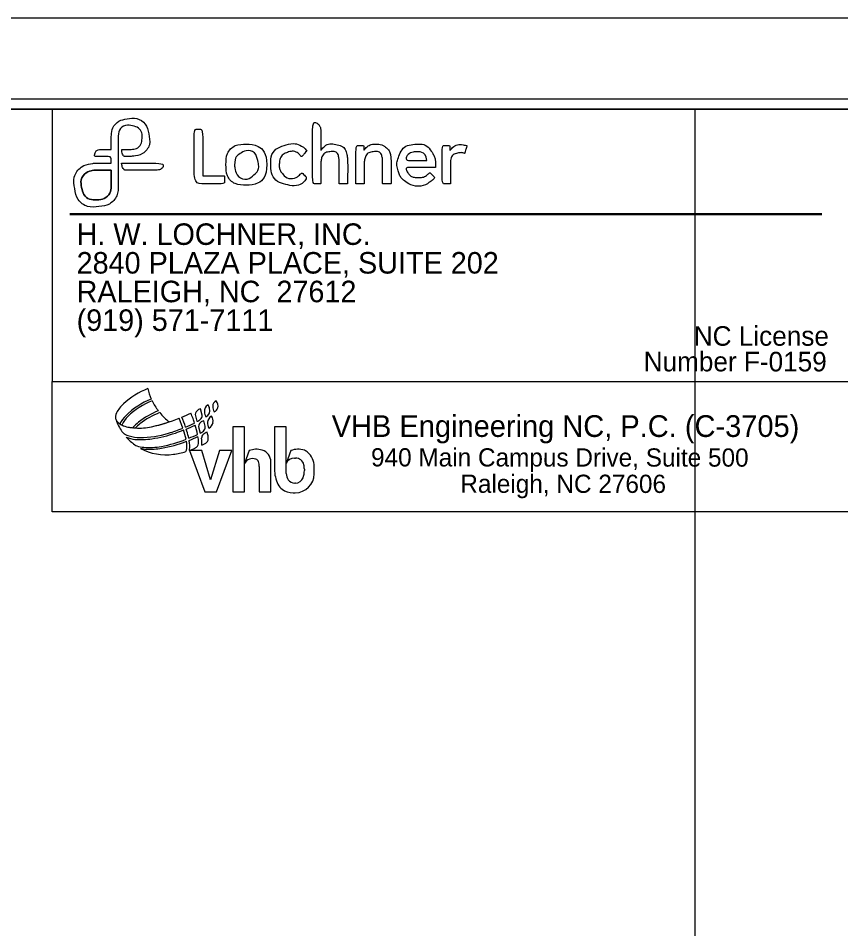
# Model space of a CAD drawing. Extents: x 2044275 to 2045958, y 759228 to 760388.
# Drawn here: x 2045534.8 to 2045738.1, y 760098.4 to 760323.3 of the extents above; entities that cross this region are included whole.
import ezdxf

# ---------------------------------------------------------------- set-up
doc = ezdxf.new("R2010")
doc.units = 0
for name, color, linetype in [('Default', 7, 'Continuous'), ('Old_Level_1', 7, 'Continuous'), ('Old_Level_4', 7, 'Continuous'), ('Sheet Clip Boundary CELL', 7, 'Continuous'), ('Sheet Cutting Line CELL', 7, 'Continuous'), ('Sheet Plan CELL', 7, 'Continuous'), ('Sheet Plot Border Inside CELL', 7, 'Continuous'), ('Sheet Plot Border Outside CELL', 7, 'Continuous')]:
    doc.layers.add(name, color=color, linetype=linetype)

msp = doc.modelspace()

# ---------------------------------------------------------------- linework, layer by layer
at = {"layer": 'Default'}
for points in [[(2045557.79, 760287.5), (2045557.67, 760287.5), (2045557.57, 760287.5), (2045557.48, 760287.5), (2045556.39, 760287.5), (2045555.31, 760287.51), (2045554.22, 760287.5), (2045553.85, 760287.49), (2045553.48, 760287.46), (2045553.11, 760287.4), (2045550.27, 760286.91), (2045548.28, 760284.04), (2045548.8, 760281.21), (2045549.34, 760278.3), (2045551.88, 760276.43), (2045554.83, 760276.76), (2045557.44, 760277.05), (2045559.54, 760279.39), (2045559.54, 760282), (2045559.54, 760285.94), (2045559.53, 760289.87), (2045559.54, 760293.8), (2045559.54, 760295.72), (2045561.33, 760297.13), (2045563.19, 760296.67), (2045564.59, 760296.32), (2045565.56, 760294.99), (2045565.44, 760293.58), (2045565.3, 760292.1), (2045564.11, 760290.94), (2045562.63, 760290.88), (2045561.99, 760290.85), (2045561.34, 760290.87), (2045560.7, 760290.86), (2045560.6, 760290.86), (2045560.5, 760290.85), (2045560.38, 760290.84), (2045560.44, 760290.24), (2045560.58, 760289.71), (2045560.93, 760289.24), (2045560.97, 760289.18), (2045561.07, 760289.14), (2045561.14, 760289.14), (2045561.78, 760289.15), (2045562.41, 760289.12), (2045563.04, 760289.19), (2045565.68, 760289.46), (2045567.67, 760292), (2045567.06, 760294.8), (2045566.51, 760297.3), (2045564.2, 760298.82), (2045561.65, 760298.41), (2045559.65, 760298.09), (2045557.96, 760296.28), (2045557.84, 760294.26), (2045557.78, 760293.24), (2045557.82, 760292.22), (2045557.81, 760291.2), (2045557.8, 760291.1), (2045557.81, 760291), (2045557.81, 760290.86), (2045557.68, 760290.86), (2045557.58, 760290.86), (2045557.49, 760290.86), (2045556.77, 760290.86), (2045556.05, 760290.87), (2045555.33, 760290.86), (2045554.58, 760290.86), (2045553.95, 760290.39), (2045553.76, 760289.67), (2045553.71, 760289.5), (2045553.71, 760289.32), (2045553.69, 760289.12), (2045555.09, 760289.12), (2045556.43, 760289.12), (2045557.79, 760289.12), (2045557.79, 760288.58), (2045557.79, 760288.06), (2045557.79, 760287.5)], [(2045614.16, 760282.34), (2045614.86, 760282.34), (2045615.53, 760282.34), (2045616.22, 760282.34), (2045616.22, 760282.41), (2045616.23, 760282.47), (2045616.23, 760282.53), (2045616.23, 760284.37), (2045616.24, 760286.21), (2045616.23, 760288.06), (2045616.22, 760288.45), (2045616.19, 760288.84), (2045616.12, 760289.22), (2045615.85, 760290.62), (2045615.12, 760291.67), (2045613.67, 760292.02), (2045612.17, 760292.39), (2045610.82, 760292.07), (2045609.77, 760290.85), (2045609.73, 760290.79), (2045609.68, 760290.74), (2045609.57, 760290.63), (2045609.57, 760290.81), (2045609.57, 760290.9), (2045609.57, 760290.99), (2045609.57, 760292.57), (2045609.58, 760294.14), (2045609.57, 760295.72), (2045609.57, 760295.93), (2045609.53, 760296.15), (2045609.46, 760296.35), (2045609.18, 760297.1), (2045608.24, 760297.66), (2045607.53, 760297.5), (2045607.53, 760292.45), (2045607.53, 760287.4), (2045607.53, 760282.34), (2045608.22, 760282.34), (2045608.89, 760282.34), (2045609.57, 760282.34), (2045609.57, 760282.47), (2045609.57, 760282.57), (2045609.57, 760282.68), (2045609.57, 760284.15), (2045609.57, 760285.62), (2045609.58, 760287.09), (2045609.58, 760287.46), (2045609.61, 760287.84), (2045609.68, 760288.2), (2045609.91, 760289.4), (2045610.69, 760290.17), (2045611.84, 760290.3), (2045612.97, 760290.43), (2045613.84, 760289.95), (2045614.07, 760288.75), (2045614.12, 760288.49), (2045614.15, 760288.22), (2045614.15, 760287.95), (2045614.16, 760286.83), (2045614.16, 760285.7), (2045614.16, 760284.57), (2045614.16, 760283.84), (2045614.16, 760283.1), (2045614.16, 760282.34)], [(2045580.43, 760284.32), (2045580.43, 760288.19), (2045580.43, 760292.03), (2045580.43, 760295.87), (2045579.69, 760295.87), (2045578.99, 760295.87), (2045578.27, 760295.87), (2045578.27, 760291.36), (2045578.27, 760286.85), (2045578.27, 760282.34), (2045580.79, 760282.34), (2045583.29, 760282.34), (2045585.82, 760282.34), (2045585.82, 760282.92), (2045585.81, 760283.48), (2045585.82, 760284.04), (2045585.83, 760284.27), (2045585.77, 760284.33), (2045585.53, 760284.33), (2045583.95, 760284.32), (2045582.36, 760284.32), (2045580.77, 760284.32), (2045580.67, 760284.32), (2045580.57, 760284.32), (2045580.43, 760284.32)], [(2045596.26, 760287.11), (2045596.26, 760289.98), (2045594.09, 760292.17), (2045591.22, 760292.17), (2045588.35, 760292.17), (2045586.17, 760289.99), (2045586.17, 760287.13), (2045586.17, 760284.25), (2045588.33, 760282.06), (2045591.17, 760282.06), (2045594.09, 760282.06), (2045596.26, 760284.21), (2045596.26, 760287.11)], [(2045606.12, 760290.48), (2045605.02, 760291.98), (2045602.63, 760292.59), (2045600.52, 760291.86), (2045598.38, 760291.11), (2045597.12, 760289.12), (2045597.25, 760286.68), (2045597.36, 760284.54), (2045598.83, 760282.73), (2045600.91, 760282.23), (2045603.05, 760281.71), (2045605.13, 760282.35), (2045606.2, 760283.82), (2045605.77, 760284.27), (2045605.35, 760284.72), (2045604.96, 760285.13), (2045604.79, 760284.99), (2045604.63, 760284.87), (2045604.49, 760284.73), (2045603.25, 760283.54), (2045601.08, 760283.67), (2045600.02, 760285.02), (2045599.46, 760285.73), (2045599.31, 760286.55), (2045599.36, 760287.44), (2045599.44, 760288.66), (2045600.24, 760289.76), (2045601.36, 760290.14), (2045602.53, 760290.55), (2045603.84, 760290.19), (2045604.66, 760289.24), (2045604.7, 760289.19), (2045604.74, 760289.13), (2045604.82, 760289.02), (2045605.27, 760289.52), (2045605.68, 760289.99), (2045606.12, 760290.48)], [(2045618.25, 760282.34), (2045618.94, 760282.34), (2045619.62, 760282.34), (2045620.31, 760282.34), (2045620.31, 760282.46), (2045620.31, 760282.57), (2045620.31, 760282.67), (2045620.31, 760284.18), (2045620.3, 760285.68), (2045620.31, 760287.19), (2045620.31, 760287.52), (2045620.34, 760287.85), (2045620.4, 760288.17), (2045620.62, 760289.38), (2045621.41, 760290.16), (2045622.56, 760290.3), (2045623.65, 760290.43), (2045624.55, 760289.99), (2045624.79, 760288.78), (2045624.84, 760288.54), (2045624.88, 760288.29), (2045624.88, 760288.04), (2045624.88, 760286.24), (2045624.88, 760284.44), (2045624.88, 760282.64), (2045624.88, 760282.54), (2045624.88, 760282.44), (2045624.88, 760282.34), (2045625.59, 760282.34), (2045626.27, 760282.34), (2045626.95, 760282.34), (2045626.95, 760282.45), (2045626.95, 760282.55), (2045626.95, 760282.64), (2045626.95, 760284.34), (2045626.96, 760286.04), (2045626.95, 760287.73), (2045626.95, 760288.11), (2045626.94, 760288.5), (2045626.9, 760288.87), (2045626.78, 760289.89), (2045626.41, 760290.8), (2045625.58, 760291.46), (2045625, 760291.92), (2045624.31, 760292.12), (2045623.58, 760292.15), (2045622.31, 760292.21), (2045621.22, 760291.83), (2045620.4, 760290.82), (2045620.37, 760290.78), (2045620.33, 760290.74), (2045620.24, 760290.65), (2045620.24, 760291.09), (2045620.24, 760291.48), (2045620.24, 760291.87), (2045619.56, 760291.87), (2045618.92, 760291.87), (2045618.25, 760291.87), (2045618.25, 760288.69), (2045618.25, 760285.53), (2045618.25, 760282.34)], [(2045637.94, 760286.41), (2045637.94, 760286.76), (2045637.95, 760287.08), (2045637.94, 760287.4), (2045637.88, 760288.34), (2045637.66, 760289.23), (2045637.15, 760290.03), (2045636.16, 760291.6), (2045634.71, 760292.28), (2045632.87, 760292.14), (2045630.9, 760291.99), (2045629.57, 760290.94), (2045628.87, 760289.12), (2045628.38, 760287.86), (2045628.39, 760286.56), (2045628.8, 760285.28), (2045629.1, 760284.35), (2045629.65, 760283.59), (2045630.43, 760283.02), (2045632.23, 760281.7), (2045635.05, 760281.73), (2045636.9, 760283.08), (2045637.21, 760283.31), (2045637.49, 760283.58), (2045637.8, 760283.85), (2045637.36, 760284.32), (2045636.97, 760284.74), (2045636.56, 760285.17), (2045636.48, 760285.1), (2045636.41, 760285.04), (2045636.34, 760284.97), (2045635.49, 760284.22), (2045634.5, 760283.86), (2045633.36, 760283.93), (2045632.42, 760283.98), (2045631.62, 760284.33), (2045631.08, 760285.13), (2045630.82, 760285.5), (2045630.67, 760285.92), (2045630.64, 760286.41), (2045631.88, 760286.41), (2045633.08, 760286.41), (2045634.29, 760286.41), (2045635.5, 760286.41), (2045636.71, 760286.41), (2045637.94, 760286.41)], [(2045645.65, 760291.72), (2045645.65, 760291.76), (2045645.65, 760291.79), (2045645.65, 760291.82), (2045645.61, 760291.83), (2045645.56, 760291.83), (2045645.52, 760291.84), (2045644.01, 760292.21), (2045642.67, 760291.95), (2045641.6, 760290.74), (2045641.58, 760290.72), (2045641.55, 760290.71), (2045641.48, 760290.68), (2045641.48, 760291.1), (2045641.48, 760291.48), (2045641.48, 760291.87), (2045640.82, 760291.87), (2045640.2, 760291.87), (2045639.57, 760291.87), (2045639.57, 760288.68), (2045639.57, 760285.51), (2045639.57, 760282.34), (2045640.26, 760282.34), (2045640.92, 760282.34), (2045641.62, 760282.34), (2045641.62, 760282.45), (2045641.62, 760282.55), (2045641.62, 760282.65), (2045641.62, 760284.28), (2045641.62, 760285.91), (2045641.62, 760287.53), (2045641.63, 760288.84), (2045642.48, 760289.82), (2045643.77, 760290.03), (2045644.25, 760290.11), (2045644.7, 760290.04), (2045645.16, 760289.86), (2045645.19, 760289.95), (2045645.21, 760290.04), (2045645.23, 760290.12), (2045645.37, 760290.65), (2045645.51, 760291.19), (2045645.65, 760291.72)], [(2045588.27, 760286.98), (2045588.31, 760288.2), (2045588.65, 760289.15), (2045589.58, 760289.8), (2045591.01, 760290.8), (2045593.51, 760290.37), (2045594.06, 760287.99), (2045594.34, 760286.75), (2045594.13, 760285.59), (2045593.18, 760284.68), (2045591.56, 760283.15), (2045588.92, 760283.99), (2045588.39, 760286.18), (2045588.32, 760286.48), (2045588.3, 760286.8), (2045588.27, 760286.98)], [(2045635.77, 760288.1), (2045634.08, 760288.1), (2045632.38, 760288.1), (2045630.69, 760288.1), (2045630.57, 760289.04), (2045631.77, 760290.19), (2045632.97, 760290.28), (2045634.53, 760290.39), (2045635.74, 760289.46), (2045635.77, 760288.1)], [(2045560.39, 760287.49), (2045560.45, 760286.9), (2045560.6, 760286.36), (2045560.95, 760285.9), (2045561.01, 760285.83), (2045561.14, 760285.78), (2045561.24, 760285.78), (2045563.85, 760285.77), (2045566.46, 760285.76), (2045569.07, 760285.77), (2045570.01, 760285.78), (2045570.79, 760286.63), (2045570.65, 760287.49), (2045567.24, 760287.49), (2045563.84, 760287.49), (2045560.39, 760287.49)], [(2045557.79, 760285.76), (2045557.69, 760285.76), (2045557.62, 760285.77), (2045557.55, 760285.77), (2045556.4, 760285.77), (2045555.24, 760285.77), (2045554.09, 760285.77), (2045553.87, 760285.77), (2045553.64, 760285.74), (2045553.42, 760285.7), (2045551.5, 760285.37), (2045550.13, 760283.37), (2045550.51, 760281.48), (2045550.89, 760279.6), (2045552.4, 760278.39), (2045554.32, 760278.45), (2045556.12, 760278.49), (2045557.72, 760280.03), (2045557.79, 760281.82), (2045557.83, 760283.08), (2045557.8, 760284.35), (2045557.8, 760285.61), (2045557.8, 760285.65), (2045557.79, 760285.69), (2045557.79, 760285.76)], [(2045557.79, 760285.76), (2045557.79, 760285.69), (2045557.8, 760285.65), (2045557.8, 760285.61), (2045557.8, 760284.35), (2045557.83, 760283.08), (2045557.79, 760281.82), (2045557.72, 760280.03), (2045556.12, 760278.49), (2045554.32, 760278.45), (2045552.4, 760278.39), (2045550.89, 760279.6), (2045550.51, 760281.48), (2045550.13, 760283.37), (2045551.5, 760285.37), (2045553.42, 760285.7), (2045553.64, 760285.74), (2045553.87, 760285.77), (2045554.09, 760285.77), (2045555.24, 760285.77), (2045556.4, 760285.77), (2045557.55, 760285.77), (2045557.62, 760285.77), (2045557.69, 760285.76), (2045557.79, 760285.76)], [(2045557.79, 760285.76), (2045557.79, 760285.69), (2045557.8, 760285.65), (2045557.8, 760285.61), (2045557.8, 760284.35), (2045557.83, 760283.08), (2045557.79, 760281.82), (2045557.72, 760280.03), (2045556.12, 760278.49), (2045554.32, 760278.45), (2045552.4, 760278.39), (2045550.89, 760279.6), (2045550.51, 760281.48), (2045550.13, 760283.37), (2045551.5, 760285.37), (2045553.42, 760285.7), (2045553.64, 760285.74), (2045553.87, 760285.77), (2045554.09, 760285.77), (2045555.24, 760285.77), (2045556.4, 760285.77), (2045557.55, 760285.77), (2045557.62, 760285.77), (2045557.69, 760285.76), (2045557.79, 760285.76)]]:
    msp.add_open_spline(points, degree=3, dxfattribs=at)
at = {"layer": 'Old_Level_1'}
for p, q in [((2045547.59, 760275.01), (2045733.35, 760275.01)), ((2045547.59, 760274.82), (2045733.35, 760274.82))]:
    msp.add_line(p, q, dxfattribs=at)
at = {"layer": 'Old_Level_4'}
for p, q in [((2045543.25, 760300.8), (2045543.25, 760233.57)), ((2045543.25, 760233.57), (2045741.31, 760233.57)), ((2045543.25, 760201.37), (2045543.25, 760233.57)), ((2045543.25, 760233.57), (2045741.31, 760233.57)), ((2045580.28, 760225.24), (2045579.85, 760226.78)), ((2045575.52, 760222.03), (2045574.64, 760224.47)), ((2045578.61, 760225.09), (2045578.99, 760223.73)), ((2045579.45, 760222.06), (2045579.8, 760220.82)), ((2045581.04, 760222.52), (2045580.66, 760223.86)), ((2045590.77, 760222.35), (2045587.88, 760222.35)), ((2045587.88, 760222.35), (2045587.88, 760206.34)), ((2045601.04, 760222.35), (2045598.16, 760222.35)), ((2045598.16, 760222.35), (2045598.16, 760211.85)), ((2045577.12, 760216.47), (2045578.59, 760217.12)), ((2045580.2, 760216.47), (2045577.12, 760216.47)), ((2045577.12, 760216.47), (2045580.92, 760206.34)), ((2045582.37, 760209.24), (2045580.2, 760216.47)), ((2045584.54, 760216.47), (2045582.37, 760209.24)), ((2045583.82, 760206.34), (2045587.62, 760216.47)), ((2045587.62, 760216.47), (2045584.54, 760216.47)), ((2045591.89, 760216.47), (2045590.77, 760213.27)), ((2045602.17, 760216.47), (2045601.04, 760213.27)), ((2045597.28, 760206.34), (2045597.28, 760213.69)), ((2045603.08, 760214.64), (2045603.35, 760214.64)), ((2045594.39, 760212.54), (2045594.39, 760206.34)), ((2045605.53, 760211.86), (2045605.53, 760211.54)), ((2045607.96, 760210.74), (2045607.96, 760212.57)), ((2045603.34, 760208.45), (2045603.16, 760208.45)), ((2045580.92, 760206.34), (2045583.82, 760206.34)), ((2045587.88, 760206.34), (2045590.77, 760206.34)), ((2045594.39, 760206.34), (2045597.28, 760206.34)), ((2045602.73, 760206.06), (2045603.29, 760206.06)), ((2045741.31, 760201.37), (2045543.25, 760201.37))]:
    msp.add_line(p, q, dxfattribs=at)
for points in [[(2045590.77, 760206.34), (2045590.77, 760213.27), (2045590.77, 760222.35)], [(2045601.04, 760210.81), (2045601.04, 760213.27), (2045601.04, 760222.35)]]:
    msp.add_lwpolyline(points, dxfattribs=at)
for centre, major_axis, start_param, end_param in [((2045574.23, 760213.28), (19.94, 0), 1.950459, 2.306295), ((2045581.14, 760235.19), (14.69, 0), 3.374816, 3.559712), ((2045575, 760211.23), (19.42, 0), 1.955908, 2.345415), ((2045575, 760211.23), (18.92, 0), 1.954608, 2.331375), ((2045581.14, 760235.19), (14.69, 0), 3.593328, 3.791245), ((2045584.27, 760227.48), (1.36, 0), 1.950799, 3.19085), ((2045582.31, 760227.54), (1.89, 0), 6.010502, 6.978239), ((2045566.27, 760222.07), (8.08, 0), 2.306295, 2.663056), ((2045577.34, 760206.86), (20.99, 0), 1.956929, 2.223843), ((2045580.01, 760225.31), (1.42, 0), 2.340862, 3.293303), ((2045580.26, 760225.04), (1.78, 0), 1.805558, 2.340862), ((2045582.59, 760226.23), (1.78, 0), 2.069357, 3.26373), ((2045580.43, 760226.41), (1.78, 0), 5.158115, 6.583255), ((2045578.83, 760225.91), (3.46, 0), 0.300085, 0.573578), ((2045586.37, 760227.59), (3.46, 0), 3.190836, 3.597778), ((2045582.72, 760227.43), (1.47, 0), 5.088672, 6.010509), ((2045560.96, 760224.82), (2.1, 0), 2.663056, 3.487291), ((2045571.33, 760228.56), (13.12, 0), 3.487291, 3.49224), ((2045560, 760224.41), (1.05, 0), 3.492238, 3.942132), ((2045560, 760224.41), (1.05, 0), 3.492238, 3.942132), ((2045571.33, 760228.56), (13.12, 0), 3.492238, 3.737263), ((2045566.56, 760219.86), (7.35, 0), 2.345415, 2.685879), ((2045566.66, 760220), (6.82, 0), 2.331375, 2.717794), ((2045577.34, 760206.86), (20.46, 0), 1.949325, 2.223843), ((2045559.01, 760263.44), (41.98, 0), 4.923489, 5.093727), ((2045581.14, 760235.19), (14.69, 0), 3.829221, 4.05458), ((2045559.01, 760263.44), (41.98, 0), 5.110242, 5.168312), ((2045526.54, 760205.28), (52.48, 0), 0.330018, 0.379866), ((2045526.54, 760205.28), (54.92, 0), 0.355324, 0.381952), ((2045552.65, 760214.96), (27.07, 0), 0.312292, 0.355324), ((2045578.62, 760225.47), (1.78, 0), 4.922279, 5.445148), ((2045578.87, 760225.2), (1.42, 0), 5.445151, 6.311085), ((2045584.26, 760226.43), (3.46, 0), 3.26373, 3.631752), ((2045583.3, 760223.43), (1.68, 0), 1.982585, 3.114577), ((2045580.79, 760223.75), (2.2, 0), 6.124862, 6.873863), ((2045562.85, 760227.35), (5.14, 0), 3.942115, 4.117328), ((2045562.85, 760227.35), (5.14, 0), 3.942115, 4.535322), ((2045562.85, 760227.35), (5.14, 0), 4.225969, 4.535322), ((2045564.62, 760237.27), (15.22, 0), 4.535322, 4.613027), ((2045564.62, 760237.27), (15.22, 0), 4.535322, 4.657076), ((2045570.33, 760216.03), (9.45, 0), 2.223843, 2.440018), ((2045570.33, 760216.03), (8.91, 0), 2.223843, 2.396036), ((2045564.62, 760237.27), (15.22, 0), 4.657076, 4.923489), ((2045564.62, 760237.27), (15.22, 0), 4.657076, 4.923489), ((2045559.01, 760263.44), (41.98, 0), 4.923489, 5.030725), ((2045559.01, 760263.44), (44.58, 0), 5.007435, 5.091777), ((2045559.01, 760263.44), (44.6, 0), 5.107726, 5.162272), ((2045559.01, 760263.44), (45.1, 0), 5.106941, 5.160619), ((2045526.54, 760205.28), (52.48, 0), 0.309699, 0.320394), ((2045552.65, 760214.96), (27.07, 0), 0.205325, 0.293478), ((2045580.77, 760222.41), (1.36, 0), 2.294387, 3.400315), ((2045581.19, 760221.94), (1.99, 0), 1.838184, 2.294391), ((2045579.68, 760222.35), (1.36, 0), 5.669754, 6.410867), ((2045584.56, 760223.4), (2.94, 0), 3.114567, 3.617561), ((2045581.21, 760223.68), (1.78, 0), 5.137017, 6.124854), ((2045562.21, 760222.38), (2.1, 0), 3.737263, 4.155114), ((2045563.43, 760224.34), (4.41, 0), 4.155114, 4.433304), ((2045564.25, 760225.74), (6.51, 0), 4.281835, 4.626581), ((2045571.33, 760228.56), (13.12, 0), 3.869789, 4.084312), ((2045564.88, 760229.38), (9.66, 0), 4.433304, 4.717272), ((2045564.8, 760244.39), (24.67, 0), 4.717272, 5.007435), ((2045562.74, 760252.59), (33.59, 0), 4.866042, 5.043468), ((2045559.01, 760263.44), (45.06, 0), 5.043468, 5.091439), ((2045561.87, 760216.58), (14.69, 0), 0.186675, 0.34709), ((2045561.87, 760216.58), (15.39, 0), 0.192744, 0.309699), ((2045559.01, 760263.44), (47.44, 0), 5.100586, 5.150688), ((2045559.01, 760263.44), (47.96, 0), 5.098273, 5.148033), ((2045552.65, 760214.96), (27.07, 0), 0.162521, 0.185756), ((2045579.17, 760222.71), (1.99, 0), 5.034707, 5.66976), ((2045581.3, 760219.61), (1.15, 0), 2.288613, 3.208516), ((2045571.51, 760218.41), (8.71, 0), 6.218327, 6.411973), ((2045582.48, 760218.27), (2.94, 0), 1.905419, 2.288613), ((2045576.65, 760219.36), (5.14, 0), 6.258511, 6.615609), ((2045564.86, 760219.64), (2.1, 0), 4.084312, 4.375641), ((2045565.2, 760236.72), (17.53, 0), 4.626581, 4.866042), ((2045566.42, 760224.1), (6.82, 0), 4.375641, 4.631331), ((2045567.2, 760233.72), (16.48, 0), 4.631331, 4.896065), ((2045564.46, 760248.48), (31.49, 0), 4.896065, 5.098239), ((2045565.41, 760246.07), (29.39, 0), 4.878361, 5.095384), ((2045573.38, 760217.51), (3.15, 0), 5.862276, 6.364042), ((2045561.87, 760216.58), (14.69, 0), 0.080866, 0.152313), ((2045561.87, 760216.58), (15.39, 0), 0.08898, 0.158557), ((2045571.97, 760217.48), (5.25, 0), 6.089473, 6.37216), ((2045578.03, 760218.37), (1.36, 0), 5.129856, 6.17953), ((2045575.22, 760218.66), (4.2, 0), 6.17953, 6.445706), ((2045579.4, 760220.67), (2.94, 0), 4.991009, 5.49053), ((2045580.65, 760219.4), (1.15, 0), 5.49053, 6.137671), ((2045566.97, 760226.5), (9.66, 0), 4.511808, 4.670453), ((2045571.33, 760228.56), (13.12, 0), 4.213149, 4.853258), ((2045567.32, 760234.68), (17.84, 0), 4.670453, 4.878361), ((2045570, 760237.91), (22.57, 0), 4.853258, 4.99278), ((2045593.69, 760211.94), (4.88, 0), 1.271815, 1.948427), ((2045594.23, 760213.69), (3.04, 0), 6.283185, 7.555001), ((2045603.97, 760211.94), (4.88, 0), 1.243417, 1.948427), ((2045604.73, 760214.17), (2.52, 0), 0.841181, 1.243417), ((2045603.29, 760212.57), (4.67, 0), 0, 0.841181), ((2045592.76, 760212.33), (-2.2, 0), 4.330931, 5.84316), ((2045593.19, 760213.4), (-1.05, 0), 3.478495, 4.330931), ((2045590.72, 760212.54), (3.67, 0), 0, 0.336903), ((2045603.08, 760212.44), (2.2, 0), 1.570796, 2.75299), ((2045603.35, 760212.54), (2.1, 0), 0.218399, 1.570796), ((2045600.28, 760211.86), (5.25, 0), 6.283185, 6.501584), ((2045606.55, 760211.85), (-8.4, 0), 0, 0.452165), ((2045603.67, 760210.81), (-2.62, 0), 6.283185, 6.906012), ((2045603.29, 760210.74), (4.67, 0), 4.712389, 6.283185), ((2045600.28, 760211.54), (5.25, 0), 5.93764, 6.283185), ((2045603.16, 760210.44), (-1.99, 0), 0.622827, 1.570796), ((2045603.34, 760210.44), (1.99, 0), 4.712389, 5.93764), ((2045602.02, 760209.65), (-3.36, 0), 0.452165, 0.946963), ((2045602.73, 760210.64), (-4.58, 0), 0.946963, 1.570796)]:
    msp.add_ellipse(centre, major_axis=major_axis, ratio=0.999914, start_param=start_param, end_param=end_param, dxfattribs=at)
at = {"layer": 'Sheet Clip Boundary CELL'}
msp.add_lwpolyline([(2044491.34, 759250.8), (2045891.35, 759250.8), (2045891.35, 760089.31), (2045702.09, 760089.31), (2045702.09, 760300.8), (2044491.34, 760300.8)], close=True, dxfattribs=at)
at = {"layer": 'Sheet Cutting Line CELL'}
msp.add_line((2045958.35, 760323.28), (2044274.85, 760323.28), dxfattribs=at)
at = {"layer": 'Sheet Plan CELL'}
for points in [[(2044441.34, 759250.8), (2044441.32, 760300.77), (2045741.3, 760300.81), (2045741.32, 760150.75), (2045941.35, 760150.73), (2045941.35, 759250.8)], [(2045941.38, 760300.8), (2044441.34, 760300.8), (2044441.34, 759250.8), (2045941.35, 759250.8)]]:
    msp.add_lwpolyline(points, close=True, dxfattribs=at)
at = {"layer": 'Sheet Plot Border Inside CELL'}
msp.add_lwpolyline([(2044287.85, 759248.28), (2045953.84, 759248.3), (2045953.85, 760303.28), (2044287.85, 760303.28)], close=True, dxfattribs=at)
at = {"layer": 'Sheet Plot Border Outside CELL'}
msp.add_lwpolyline([(2044274.85, 759228.28), (2045958.35, 759228.28), (2045958.35, 760323.28), (2044274.85, 760323.28)], close=True, dxfattribs=at)

# ---------------------------------------------------------------- texts
at = {"layer": 'Old_Level_1'}
for s, height, p in [('H. W. LOCHNER, INC.', 5.3144, (2045549.27, 760267.29)), ('2840 PLAZA PLACE, SUITE 202', 5.3144, (2045549.27, 760260.21)), ('2840 PLAZA PLACE, SUITE 202', 5.3144, (2045549.27, 760260.21)), ('RALEIGH, NC  27612', 5.3144, (2045549.27, 760253.13)), ('(919) 571-7111', 5.3144, (2045549.27, 760246.05)), ('NC License', 4.831, (2045701.74, 760242.38)), ('Number F-0159', 4.8312, (2045689.36, 760236.05))]:
    msp.add_text(s, height=height, rotation=0, dxfattribs=at).set_placement(p)
at = {"layer": 'Old_Level_4'}
msp.add_text('VHB Engineering NC, P.C. (C-3705)', height=5.3606, dxfattribs=at).set_placement((2045612.29, 760219.86))
for s, p in [('940 Main Campus Drive, Suite 500', (2045622.01, 760212.58)), ('Raleigh, NC 27606', (2045644.06, 760206.06))]:
    msp.add_text(s, height=4.4983, rotation=359.9612, dxfattribs=at).set_placement(p)

doc.saveas('drawing.dxf')
